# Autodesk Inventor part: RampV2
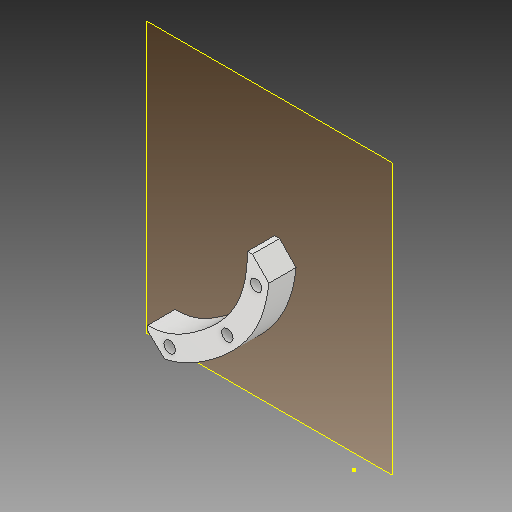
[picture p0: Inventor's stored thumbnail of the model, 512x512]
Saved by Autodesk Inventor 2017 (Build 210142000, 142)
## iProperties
Created: 2017-04
Part Number: RampV2
Material: ABS Plastic
Document SubType Name: Modeling
Designer: 1460374
Density: 1.06 g/cm^3
Appearance: Smooth - White
Author: 1460374
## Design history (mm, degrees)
workplane "Work Plane1"
sketch "Sketch1" dims "d0" = 7.62
  geometry: L1 (-117.357, 5.198)-(-117.357, 12.818); L2 (-60.667, 77.597)-(-53.047, 77.597); 4 further points
  constraints: 4 end point, 1 horizontal, 1 vertical, 8 other
extrude "Extrusion1" new body sketch "Sketch1" distance "d1" = 15.5; taper "d2" = 0 deg
chamfer "Chamfer1" distance "d3" = 4.7625; stored, may be unused: second distance "d4" = 3.175, angle "d5" = 45 deg
chamfer "Chamfer2" distance "d6" = 4.7625; stored, may be unused: second distance "d7" = 3.175, angle "d8" = 45 deg
sketch "Sketch2"
  geometry: 1 further point
thicken "Thicken1" dims "d9" = 2.54, "d10" = 2.54
sketch "Sketch4"
  geometry: C1 r 3.225 at (-104.916, 8.353); C2 r 3.225 at (-72.045, 30.571); C3 r 3.225 at (-55.67, 63.321); 1 further point
  constraints: 3 centre point
  dimensions: "d11" = 6.45 diameter of C1; "d12" = 6.45 diameter of C2; "d13" = 6.45 diameter of C3
thicken "Thicken2" dims "d14" = 2.54, "d15" = 2.54
extrude "Extrusion2" cut sketch "Sketch4" distance "d16" = 16.25001; taper "d17" = 0 deg
body "Solid1"
